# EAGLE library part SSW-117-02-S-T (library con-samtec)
THROUGH-HOLE .025" SQ POST SOCKET Source: Samtec SSW.pdf
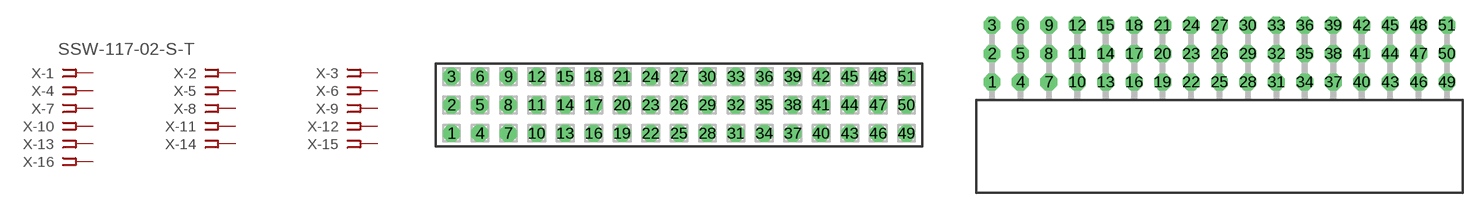
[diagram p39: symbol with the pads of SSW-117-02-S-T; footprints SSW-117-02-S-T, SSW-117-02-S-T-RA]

Designator prefix X; gates -1=FPINV -2=FPIN -3=FPIN -4=FPIN -5=FPIN -6=FPIN -7=FPIN -8=FPIN -9=FPIN -10=FPIN -11=FPIN -12=FPIN -13=FPIN -14=FPIN -15=FPIN -16=FPIN -17=FPIN -18=FPIN -19=FPIN -20=FPIN -21=FPIN -22=FPIN -23=FPIN -24=FPIN -25=FPIN -26=FPIN -27=FPIN -28=FPIN -29=FPIN -30=FPIN -31=FPIN -32=FPIN -33=FPIN -34=FPIN -35=FPIN -36=FPIN -37=FPIN -38=FPIN -39=FPIN -40=FPIN -41=FPIN -42=FPIN -43=FPIN -44=FPIN -45=FPIN -46=FPIN -47=FPIN -48=FPIN -49=FPIN -50=FPIN -51=FPIN

## SSW-117-02-S-T (MPN: SSW-117-02-S-T; OC_FARNELL: unknown; OC_NEWARK: 82P7592)  [SSW-117-02-S-T]
1  -1:1  pas
2  -2:1  pas
3  -3:1  pas
4  -4:1  pas
5  -5:1  pas
6  -6:1  pas
7  -7:1  pas
8  -8:1  pas
9  -9:1  pas
10  -10:1  pas
11  -11:1  pas
12  -12:1  pas
13  -13:1  pas
14  -14:1  pas
15  -15:1  pas
16  -16:1  pas
17  -17:1  pas
18  -18:1  pas
19  -19:1  pas
20  -20:1  pas
21  -21:1  pas
22  -22:1  pas
23  -23:1  pas
24  -24:1  pas
25  -25:1  pas
26  -26:1  pas
27  -27:1  pas
28  -28:1  pas
29  -29:1  pas
30  -30:1  pas
31  -31:1  pas
32  -32:1  pas
33  -33:1  pas
34  -34:1  pas
35  -35:1  pas
36  -36:1  pas
37  -37:1  pas
38  -38:1  pas
39  -39:1  pas
40  -40:1  pas
41  -41:1  pas
42  -42:1  pas
43  -43:1  pas
44  -44:1  pas
45  -45:1  pas
46  -46:1  pas
47  -47:1  pas
48  -48:1  pas
49  -49:1  pas
50  -50:1  pas
51  -51:1  pas

## SSW-117-02-S-TRA (MPN: SSW-117-02-S-T-RA; OC_FARNELL: unknown; OC_NEWARK: 82P7593)  [SSW-117-02-S-T-RA]
Pads as for SSW-117-02-S-T

## Footprint SSW-117-02-S-T (pad centres in mm)
THROUGH-HOLE .025" SQ POST SOCKET Source: Samtec SSW.pdf
drill 1 pad 1.5 octagon: 1 -20.32,-2.54; 2 -20.32,0; 3 -20.32,2.54; 4 -17.78,-2.54; 5 -17.78,0; 6 -17.78,2.54; 7 -15.24,-2.54; 8 -15.24,0; 9 -15.24,2.54; 10 -12.7,-2.54; 11 -12.7,0; 12 -12.7,2.54; 13 -10.16,-2.54; 14 -10.16,0; 15 -10.16,2.54; 16 -7.62,-2.54; 17 -7.62,0; 18 -7.62,2.54; 19 -5.08,-2.54; 20 -5.08,0; 21 -5.08,2.54; 22 -2.54,-2.54; 23 -2.54,0; 24 -2.54,2.54; 25 0,-2.54; 26 0,0; 27 0,2.54; 28 2.54,-2.54; 29 2.54,0; 30 2.54,2.54; 31 5.08,-2.54; 32 5.08,0; 33 5.08,2.54; 34 7.62,-2.54; 35 7.62,0; 36 7.62,2.54; 37 10.16,-2.54; 38 10.16,0; 39 10.16,2.54; 40 12.7,-2.54; 41 12.7,0; 42 12.7,2.54; 43 15.24,-2.54; 44 15.24,0; 45 15.24,2.54; 46 17.78,-2.54; 47 17.78,0; 48 17.78,2.54; 49 20.32,-2.54; 50 20.32,0; 51 20.32,2.54

## Footprint SSW-117-02-S-T-RA (pad centres in mm)
THROUGH-HOLE .025" SQ POST SOCKET Source: Samtec SSW.pdf
drill 1 pad 1.5 octagon: 1 -20.32,1.524; 2 -20.32,4.064; 3 -20.32,6.604; 4 -17.78,1.524; 5 -17.78,4.064; 6 -17.78,6.604; 7 -15.24,1.524; 8 -15.24,4.064; 9 -15.24,6.604; 10 -12.7,1.524; 11 -12.7,4.064; 12 -12.7,6.604; 13 -10.16,1.524; 14 -10.16,4.064; 15 -10.16,6.604; 16 -7.62,1.524; 17 -7.62,4.064; 18 -7.62,6.604; 19 -5.08,1.524; 20 -5.08,4.064; 21 -5.08,6.604; 22 -2.54,1.524; 23 -2.54,4.064; 24 -2.54,6.604; 25 0,1.524; 26 0,4.064; 27 0,6.604; 28 2.54,1.524; 29 2.54,4.064; 30 2.54,6.604; 31 5.08,1.524; 32 5.08,4.064; 33 5.08,6.604; 34 7.62,1.524; 35 7.62,4.064; 36 7.62,6.604; 37 10.16,1.524; 38 10.16,4.064; 39 10.16,6.604; 40 12.7,1.524; 41 12.7,4.064; 42 12.7,6.604; 43 15.24,1.524; 44 15.24,4.064; 45 15.24,6.604; 46 17.78,1.524; 47 17.78,4.064; 48 17.78,6.604; 49 20.32,1.524; 50 20.32,4.064; 51 20.32,6.604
